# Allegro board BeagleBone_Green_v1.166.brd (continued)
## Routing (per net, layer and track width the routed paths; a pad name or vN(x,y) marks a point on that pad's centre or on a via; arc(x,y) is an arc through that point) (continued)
TIMER6: length 36.6
  TOP w0.121: v1(51.56,113.39) 51.05,112.88 51.05,110.08 50.8,109.83 50.8,102.84 50.32,102.36 50.32,100.74 U5.U6
  LYR4 w0.133: P8.10 32.38,116.69 49.53,116.69 50.29,115.93 50.29,114.66 v1(51.56,113.39)
TIMER7: length 34.1
  TOP w0.121: v1(49.52,99.94) U5.T7
  LYR3 w0.133: v1(49.52,99.94) 49.52,104.28 47.37,106.43 47.37,109.19 45.67,110.9 45.67,111.15 44.36,112.46 37.25,112.46 v1(36.32,113.39)
  LYR4 w0.133: v1(36.32,113.39) 35.81,113.89 30.99,113.89 29.97,114.91 29.97,116.56 P8.8
TXCLK: length 6.1
  TOP w0.121: U14.20 26.73,99.8 27.06,100.13 29.85,100.13 30,100.29 30.01,100.29 30.24,100.52 30.24,100.53 30.4,100.69 v1(30.61,100.69)
  BOTTOM w0.121: R134.2 v1(30.61,100.69)
TXN: length 20.3
  TOP w0.095: v1(22.67,97.19) 22.67,96.81 22.99,96.49 U14.28
  LYR3 w0.102: v1(22.67,97.19) 22.28,96.8 22.28,96.28 21.21,95.21 21.21,93.57 19.61,91.97 18.11,91.97 17.3,92.79 17.3,94.21 17.55,94.47 18.29,94.47 18.54,94.21 P5.6
  BOTTOM w0.095: R123.1 v1(22.67,97.19)
  BOTTOM w0.121: P5.6 C140.1
TXP: length 17.8
  TOP w0.095: U14.29 23.43,95.99 23.21,96.21 22.68,96.21 22.67,96.22 v1(22.67,96.24)
  LYR3 w0.102: v1(22.67,96.24) 21.51,95.08 21.51,93.45 19.74,91.67 17.98,91.67 16.99,92.66 16.99,95.89 P5.3
  BOTTOM w0.095: R122.1 v1(22.67,96.24)
  BOTTOM w0.121: C139.1 P5.3
U5_H18: length 4.2
  TOP w0.121: U5.H18 39.5,93.14 39.3,92.94 R28.1
U5_R13: length 8.5
  TOP w0.121: v1(43.92,99.14) U5.R13
  LYR3 w0.121: 44.11,101.79 44.32,101.58 44.32,99.54 v1(43.92,99.14)
  LYR3 w0.133: 44.11,101.79 43.66,102.24 43.66,104.35 v1(43.49,104.52)
  BOTTOM w0.133: R160.1 43.81,104.85 v1(43.49,104.52)
U5_T13: length 7.5
  TOP w0.121: v1(43.92,99.94) U5.T13
  LYR3 w0.133: v1(42.88,104.57) 42.89,104.56 42.89,104.43 43.4,103.92 43.4,101.89 43.92,101.37 v1(43.92,99.94)
  BOTTOM w0.133: v1(42.88,104.57) 42.93,104.62 R161.1
UART0_RX: length 28.4
  TOP w0.121: v1(42.32,90.34) U5.E15
  LYR4 w0.133: v1(45.01,76.45) 42.8,78.66 42.8,79.78 42.09,80.49 42.09,85.6 40.85,86.84 40.85,89.4 41.36,89.92 41.9,89.92 v1(42.32,90.34)
  BOTTOM w0.121: U15.6 54.62,76.8 53.72,77.7 51.56,77.7 50.71,76.85 45.4,76.85 v1(45.01,76.45)
UART0_TX: length 28.7
  TOP w0.121: v1(41.52,90.34) U5.E16
  LYR4 w0.133: v1(44.42,76.4) 42.56,78.26 42.56,79.38 41.81,80.14 41.81,85.5 40.59,86.72 40.59,89.51 41.41,90.34 v1(41.52,90.34)
  BOTTOM w0.121: v1(44.42,76.4) 44.42,76.78 44.81,77.17 50.52,77.17 51.31,77.95 53.98,77.95 54.62,77.3 U15.5
UART1_RXD: length 25.6
  TOP w0.121: v1(41.53,89.51) 41.53,89.55 U5.D16
  LYR4 w0.121: 42.11,86.77 41.92,86.96 41.92,89.12 v1(41.53,89.51)
  LYR4 w0.133: v1(46.48,74.02) 45.97,74.52 45.97,76.81 43.61,79.17 43.61,80.04 42.9,80.75 42.9,85.98 42.11,86.77
  BOTTOM w0.121: P9.26 50.16,70.97 49.15,70.97 47.75,72.36 47.75,73.25 46.99,74.02 v1(46.48,74.02)
UART1_TXD: length 23.3
  TOP w0.121: v1(42.32,89.54) U5.D15
  LYR4 w0.121: v1(42.32,89.54) 42.72,89.14 42.72,88.49
  LYR4 w0.133: P9.24 47.52,71.07 47.52,73.86 46.28,75.11 46.28,76.83 43.92,79.19 43.92,80.14 43.14,80.92 43.14,86.13 42.73,86.53 42.73,88.48 42.72,88.49
UART2_RXD: length 83.9
  TOP w0.121: v1(80.72,100.24) 79.44,101.53 J5.1 ; U5.A17 41.12,87.32 39.49,85.69 39.49,78.11 42.13,75.47 v1(42.13,75.34) 42.24,75.23 42.24,71.91 43.05,71.09 44.96,71.09 P9.22
  LYR3 w0.133: v1(42.13,75.34) 42.41,75.61 47.68,75.61 48.46,74.83 56,74.83 56.34,75.17 56.34,75.43 56.65,75.74 57.19,75.74 59.04,77.6 69.8,77.6 82.28,90.08 82.28,98.69 v1(80.72,100.24)
UART2_TXD: length 85.8
  TOP w0.121: v1(80.47,99.24) 80.18,99.53 J5.2 ; P9.21 45.21,68.3 45.21,69.95 44.45,70.71 42.93,70.71 41.91,71.73 41.91,74.9 v1(41.43,75.39) 39.24,77.57 39.24,85.83 40.72,87.3 40.72,87.94 U5.B17
  LYR3 w0.133: v1(80.47,99.24) 82.04,97.66 82.04,90.17 69.7,77.83 57.84,77.83 55.08,75.07 48.68,75.07 47.9,75.84 41.88,75.84 v1(41.43,75.39)
UART4_RXD: length 41.6
  TOP w0.121: v1(38.48,101.83) 38.61,101.7 38.61,101.47 38.91,101.17 38.91,101.12 40.1,99.94 40.72,99.94 U5.T17
  LYR4 w0.133: v1(38.48,101.83) 38.43,101.83 37.86,101.26 36.77,101.26 35.94,100.43 35.94,88.49 35.69,88.24 35.69,82.65 34.54,81.51 v1(34.54,71.6)
  BOTTOM w0.121: P9.11 35.05,68.3 35.05,70.52 34.54,71.03 v1(34.54,71.6)
UART4_TXD: length 44.2
  TOP w0.121: v1(33.66,71.6) 35.05,70.21 35.05,68.3 P9.13 ; v1(39.6,101.35) 39.6,101.34 39.75,101.19 39.75,101.07 40.08,100.74 40.71,100.74 U5.U17
  LYR4 w0.121: v1(39.6,101.35) 39.59,101.35
  LYR4 w0.133: v1(33.66,71.6) 33.66,81.64 35.18,83.16 35.18,88.49 35.43,88.75 35.43,101.06 37.58,103.2 38.28,103.2 38.89,102.59 38.89,101.78 39.32,101.35 39.59,101.35
USB0_DM: length 42.2
  TOP w0.114: U5.N18 40.2,97.25 40.05,97.25 39.79,97.51 39.47,97.51 39.32,97.36 38.99,97.36 38.84,97.51 38.58,97.51 38.43,97.36 38.18,97.36 37.46,98.07 37.46,99.12 36.97,99.62 36.75,99.62 36.58,99.8 36.58,100.01 36.35,100.23 36.09,100.23 35.92,100.41 35.92,100.67 35.04,101.55 33.08,101.55 32.65,101.98 22.83,101.98 16.89,107.92 14.53,107.92 14.41,107.81 14.41,107.25 14.2,107.04 U10.2 13.64,107.04 13.06,107.62 13.06,108.49 12.74,108.81 12.32,108.81 12.19,108.68 12.19,108.39 v1(12.19,108.39)
  BOTTOM w0.114: P4.2 11.97,108.61 v1(12.19,108.39)
USB0_DP: length 42.2
  TOP w0.114: v1(12.19,109.19) 12.29,109.09 12.85,109.09 13.34,108.61 13.34,107.74 13.54,107.54 U10.1 14.1,107.66 14.1,108 14.3,108.2 17.01,108.2 22.95,102.26 32.77,102.26 33.2,101.83 35.15,101.83 37.74,99.24 37.74,98.19 38.15,97.78 39.91,97.78 40.16,97.53 40.72,97.53 U5.N17
  BOTTOM w0.114: v1(12.19,109.19) 12.19,109.14 11.94,108.89 7.29,108.89 6.92,109.26 P4.3
USB0_ID: length 48.7
  TOP w0.121: v1(17.02,107.04) 16,106.02 14.1,106.02 13.98,106.15 U10.3 ; U5.P16 v1(41.52,98.34)
  LYR3 w0.133: v1(17.02,107.04) 17.1,106.95 27.15,106.95 27.76,106.35 31.7,106.35 32.56,105.49 36.25,105.49 36.91,104.83 38.02,104.83 38.89,103.96 38.89,101.27 39.54,100.62 41.31,100.62 41.54,100.39 41.65,100.39 41.89,100.15 41.89,98.71 v1(41.52,98.34)
  BOTTOM w0.121: v1(17.02,107.04) 16.94,107.11 16.94,108.1 14.76,110.29 7.26,110.29 6.89,109.91 P4.4
USB1_DM: length 54.2
  TOP w0.114: U5.R18 40.2,98.86 39.38,98.86 38.57,99.67 37.73,99.67 37.54,99.86 37.54,100.02 v1(37.62,100.1)
  LYR3 w0.127: v1(16.46,81.48) 16.46,81.41 16.18,81.13 15.82,81.13 15.39,81.55 15.39,83.31 18.39,86.31 19.66,86.31 22.66,89.31 22.66,92.23 23.47,93.04 23.47,101.04 25.12,102.69 34.7,102.69 36.02,101.37 36.91,101.37 37.36,100.91 37.36,100.51 37.62,100.25 v1(37.62,100.1)
  BOTTOM w0.114: P3.2 11.68,77.3 12.32,76.66 13.6,76.66 15.33,78.39 15.33,78.66 15.11,78.88 U9.2 15.11,79.58 15.27,79.73 15.91,79.73 16.08,79.9 16.08,81.21 16.36,81.48 v1(16.46,81.48)
USB1_DP: length 54.3
  TOP w0.114: U5.R17 41.04,98.74 40.64,99.14 39.5,99.14 38.53,100.1 v1(38.25,100.1)
  LYR3 w0.127: v1(38.25,100.1) 38.13,100.23 38.07,100.23 37.92,100.38 37.67,100.63 37.67,101.04 37.03,101.68 36.14,101.68 34.82,103 24.99,103 23.16,101.17 23.16,93.17 22.35,92.35 22.35,89.43 19.53,86.61 18.26,86.61 15.09,83.44 15.09,81.43 15.64,80.87 v1(16.54,80.87)
  BOTTOM w0.114: P3.3 12.12,76.38 13.72,76.38 15.61,78.27 U9.1 15.61,79.36 15.7,79.45 16.03,79.45 16.36,79.78 16.36,80.7 v1(16.54,80.87)
USB1_DRVVBUS: length 62.3
  TOP w0.121: U5.F15 v1(42.32,91.14)
  LYR3 w0.133: v1(3.68,71.73) 4.06,72.11 12.83,72.11 14.93,74.21 23.3,74.21 23.62,73.89 30.28,73.89 30.87,73.29 37.63,73.29 37.68,73.34 41.06,73.34 v1(41.25,73.53)
  LYR4 w0.121: v1(42.32,91.14) 41.69,91.14 40.33,89.77
  LYR4 w0.133: v1(41.25,73.53) 40.89,73.89 40.89,76.43 41.99,77.52 41.99,79.37 41.53,79.83 41.53,83.92 40.92,84.53 40.92,85.85 40.33,86.44 40.33,89.77
  BOTTOM w0.121: v1(3.68,71.73) 4.06,72.11 R53.1 4.36,72.15 U8.4
USB1_ID: length 1.9
  TOP w0.121: v1(40.72,98.34) 40.77,98.29 U5.P17
  BOTTOM w0.121: v1(40.72,98.34) 40.72,98.83 40.45,99.1 R49.2
USB1_OCN: length 65.1
  TOP w0.121: v1(41.48,99.98) 41.5,99.96 41.5,99.95 U5.T16
  LYR3 w0.121: 38.01,102.94 38.01,102.49 37.97,102.46 37.97,101.7 39.34,100.33 41.17,100.33
  LYR3 w0.133: 41.17,100.33 41.48,100.02 v1(41.48,99.98) ; v1(14.33,104.05) 18.28,104.05 18.36,104.14 23.11,104.14 23.2,104.05 35.78,104.05 36.6,103.23 37.72,103.23 38.01,102.94
  LYR4 w0.133: v1(14.33,104.05) 14.66,103.72 14.66,86.23 9.02,80.59 3.33,80.59 v1(3.17,80.75)
  BOTTOM w0.121: v1(3.17,80.75) 3.56,80.37 R52.2 3.94,79.77 4.36,79.35 U8.5
USB1_PWR: length 9.8
  LYR3 w0.381: v1(7.37,79.73) 8.76,79.73 10.67,81.64 v1(14.1,81.64)
  BOTTOM w0.254: U9.6 15.61,80.5 14.48,81.64 v1(14.1,81.64)
USB1_VBUS: length 55.1
  TOP w0.305: v1(37.59,102.59) 37.97,102.21 37.97,101.63 38.57,101.03 38.57,100.95 39.99,99.54 U5.T18
  LYR3 w0.381: v1(37.59,102.59) 37.52,102.67 36.55,102.67 35.56,103.66 24.69,103.66 22.94,101.9 v1(21.03,101.9)
  LYR4 w0.381: v1(21.72,90.14) 22.1,90.53 22.1,99.54 21.03,100.61 v1(21.03,101.9)
  BOTTOM w0.381: v1(21.72,90.14) 21.72,89.26 19.05,86.59 17.65,86.59 16.51,85.45 7.87,85.45 5.33,82.91 FB8.1
USB_DC: length 26.5
  TOP w0.254: v1(16.13,107.26) 16.05,107.26 15.78,107.54 U10.6
  LYR3 w0.381: v1(38.25,103.63) 38.25,103.78 37.64,104.39 36.7,104.39 36.12,104.98 32.49,104.98 31.72,105.74 30,105.74 29.68,105.41 28.01,105.41 27.03,106.4 16.89,106.4 16.13,107.16 v1(16.13,107.26)
  BOTTOM w0.381: R159.1 38.4,103.48 v1(38.25,103.63)
  vias: v1(20.7,76.53) v1(20.65,75.95) v1(21.21,76.17) v2(12.57,107.29) v2(12.6,106.27) v2(13.34,106.25)
USR0: length 25.9
  TOP w0.121: Q1.2 21.34,108.05 21.72,107.67 22.86,107.67 R76.1 24.03,107.16 26.04,105.16 26.04,104.78 27.61,103.2 35.38,103.2 36.3,104.11 38.35,104.11 38.73,103.73 38.73,103.61 39.42,102.92 41.27,102.92 42.72,101.48 U5.V15
USR1: length 30.5
  TOP w0.121: Q1.5 21.34,110.85 21.59,111.1 22.86,111.1 R77.1 24.13,109.83 24.13,107.47 26.31,105.28 26.31,104.88 27.74,103.45 35.2,103.45 36.12,104.37 38.48,104.37 39.52,103.33 41.25,103.33 43.12,101.46 43.12,100.74 U5.U15
USR2: length 31.6
  TOP w0.121: R78.1 19.94,106.53 v1(18.92,107.54) 18.67,107.8 Q2.2 ; U5.T15 42.31,99.94 v1(42.3,99.94)
  LYR3 w0.133: v1(42.3,99.94) 42.3,100.1 41.48,100.92 40.79,100.92 39.8,101.9 39.8,102.21 39.22,102.79 39.22,104.01 38.02,105.21 36.93,105.21 36.37,105.77 32.72,105.77 31.29,107.19 29.64,107.19 29.63,107.19 29.3,107.19 29.29,107.19 19.28,107.19 v1(18.92,107.54)
USR3: length 28.8
  TOP w0.121: U5.V16 41.92,101.93 41.2,102.64 39.2,102.64 38.61,103.23 38.09,103.23 38.06,103.26 37.35,103.26 37.32,103.29 35.85,103.29 35.51,102.95 27.44,102.95 25.55,104.84 25.55,105.26 24.21,106.6 22.66,106.6 22.58,106.53 R79.1 21.97,106.78 21.08,107.67 20.47,107.67 19.79,108.36 19.79,108.99 19.58,109.19 18.8,109.19 18.67,109.32 Q2.5
VDCDC1:
  vias: v1(21.46,75.03) v1(22.1,75.03)
VIO: length 22.4
  TOP w0.121: U2.18 24.06,76.8 23.56,76.3 v1(23.49,76.3) ; U16.5 33.8,73.25 33.11,73.94 32.08,73.94 v1(31.65,74.37)
  LYR3 w0.133: v1(23.49,76.3) 24.38,76.3 25.15,75.54 30.28,75.54 31.45,74.37 v1(31.65,74.37)
  BOTTOM w0.121: R7.2 17.78,80.59 19.53,78.84 21.84,78.84 22.61,78.08 23.11,78.08 23.49,77.7 v1(23.49,76.3)
VLDO1: length 4.5
  TOP w0.203: 20.45,81.77 U2.3
  TOP w0.254: v1(19.68,81.89) 19.81,81.77 20.45,81.77
  BOTTOM w0.381: v1(19.68,81.89) 19.05,81.25 18.8,81.25 18.8,83.03
VREFP_ADC: length 7.7
  TOP w0.121: 47.12,87.94 47.12,86.97 46.99,86.84
  TOP w0.254: 47.12,87.94 U5.B9
  TOP w0.305: 46.69,86.54 46.99,86.84
  TOP w0.381: C32.1 C31.1 C33.1 45.5,83.45 R27.2 45.5,84.66 46.61,85.77 46.61,86.46 46.69,86.54
VRTC: length 42.4
  TOP w0.254: v1(49.52,89.54) U5.D7
  LYR3 w0.381: v1(18.29,85.45) 21.97,85.45 22.35,85.83 26.92,85.83 28.7,87.6 34.54,87.6 36.57,85.58 38.83,85.58 38.84,85.57 38.99,85.57 39.77,84.79 47.48,84.79 48.7,86.02 v1(48.7,86.08)
  BOTTOM w0.178: R26.1 51.21,84.3 51.09,84.43 51.09,85.79 50.8,86.08 v1(50.61,86.08)
  BOTTOM w0.381: R5.2 C16.1 16.51,84.1 17.86,85.45 v1(18.29,85.45) ; C105.1 v1(48.7,86.08)
WAKEUP: length 63.4
  TOP w0.121: U5.C5 v1(51.12,88.73) ; v1(22.48,76.3) 22.48,76.3 22.06,76.72 U2.13
  LYR3 w0.133: v1(59.82,76.56) 57.38,74.12 48.03,74.12 47.37,74.78 43.1,74.78 42.75,74.42 35.84,74.42 35.23,73.81 31.24,73.81 30.53,74.52 25.53,74.52 24.26,75.79 22.98,75.79 v1(22.48,76.3)
  LYR4 w0.133: v1(51.12,88.73) 50.67,88.29 50.67,87.67 52.01,86.33 54.86,86.33 56.13,85.06 56.39,85.06 59.82,81.64 v1(59.82,76.56)
  BOTTOM w0.121: v1(51.12,88.73) 51.52,88.33 51.52,87.67 51.56,87.62 R26.2
WP: length 9.2
  BOTTOM w0.121: TP4.1 23.24,88.11 25.47,88.11 26.04,87.54 R156.2 26.82,87.54 26.95,87.67 26.95,88.39 27.2,88.64 28.83,88.64 29.48,87.99 U7.5
XDMA_EVENT_INTR0: length 10.7
  BOTTOM w0.121: P2.17 35.62,82.59 36.32,81.89 36.32,80.49 37.4,79.41 40.78,79.41 40.97,79.22 41.78,79.22 42.04,78.97 R18.2
YEL_C: length 3.2
  TOP w0.381: v1(5.71,93.07) 5.71,92.15 P5.11
  BOTTOM w0.381: R130.2 v1(5.71,93.07)
YELA: length 28.5
  TOP w0.254: U14.2 v1(25.23,92.56)
  BOTTOM w0.254: v1(25.23,92.56) 24.72,92.05 22.61,92.05 19.3,88.75 16.05,88.75 13.13,91.67 12.06,91.67 10.54,93.19 C164.1 C166.1 8.89,93.19 8.45,92.75 8.45,91.48 8,91.03 7.24,91.03 6.6,91.67 R135.1
  BOTTOM w0.381: P5.12 6.27,91.47 R135.1
ZQ: length 2.5
  TOP w0.121: v1(67.7,87.49) U12.L8
  BOTTOM w0.121: R99.2 68.1,87.09 v1(67.7,87.49)
N21757673: length 4.3
  BOTTOM w0.121: R11.2 C19.1 R10.1 17.53,104.62 18.29,105.38 U4.4
N21769115: length 5.9
  TOP w0.121: S2.3 S2.1 78.74,110.24 78.74,110.97 78.23,111.48 R75.2
N22155575: length 7
  TOP w0.121: v1(42.32,98.34) U5.P15
  LYR3 w0.133: v1(42.32,100.71) 42.32,100.66 42.71,100.27 42.71,98.73 v1(42.32,98.34)
  BOTTOM w0.381: R159.2 40.49,103.48 42.04,101.93 42.04,100.99 v1(42.32,100.71)
N22248684: length 1.5
  TOP w0.121: R167.1 39.88,107.92 40.58,107.23 Y4.3
N22287501: length 12.7
  TOP w0.121: v1(38.1,113.39) 38.48,113 42.04,113 42.37,112.67 U3.4
  BOTTOM w0.121: v1(38.1,113.39) 37.59,113.89 32.38,113.89 31.88,113.39 R162.1
N22287555: length 18.9
  TOP w0.121: v1(41.73,104.14) 41.38,103.78 39.45,103.78 37.46,105.77 37.46,107.47 39.07,109.07 41.53,109.07 41.72,109.26 U3.2 ; v1(43.12,99.14) U5.R14
  LYR3 w0.121: 43.52,100.81 43.52,99.54 v1(43.12,99.14)
  LYR3 w0.133: v1(41.73,104.14) 42.24,103.63 42.24,102.49 43.52,101.21 43.52,100.81
N22420400: length 9.6
  TOP w0.203: U2.4 20.3,81.37 20.19,81.25 20.48,80.97 U2.5
  TOP w0.381: 20.19,81.25 20.09,81.25 17.81,78.98 17.81,77.05 16.56,75.79 TP5.1
N22420444: length 10.1
  TOP w0.203: TP6.1 17.5,74.63 17.5,76.1 18.29,76.89 18.29,78.79 20.06,80.57 U2.6
N22420447: length 4.1
  TOP w0.203: TP7.1 18.67,75.95 19.99,77.27 19.99,77.88 20.68,78.57 U2.11
N22488252: length 24.6
  TOP w0.121: TP9.1 26.42,88.75 29.21,88.75 32.38,85.57 32.38,85.42 33.91,83.9 34.75,83.9 35.56,84.71 35.56,88.68 36.79,89.91 37.45,89.91 37.83,89.53 38.75,89.53 39.56,90.34 40.72,90.34 U5.E17
N22648410: length 8.6
  BOTTOM w0.121: U17.1 53.07,107.28 C25.1 53.72,107.29 R17.1 54.23,106.78 55.63,106.78 56.01,107.16 56.01,108.55 Y2.2
N22648422: length 8.2
  BOTTOM w0.121: U17.2 52.46,106.78 C26.1 53.85,106.15 R17.2 54.23,106.27 55.88,106.27 56.26,105.89 Y2.1
N22649826: length 1.5
  BOTTOM w0.121: U17.3 50.67,106.28 R171.2
N22650321: length 3.4
  BOTTOM w0.121: R174.1 R172.2 46.86,105.38 47.12,105.64 47.12,106.02 47.38,106.28 U17.6
N22650344: length 2.4
  BOTTOM w0.121: U17.7 46.73,106.78 R175.2 R173.1
N22650388: length 5.3
  TOP w0.121: U5.V10 46.61,101.24 46.61,102.72 46.99,103.1 v1(46.99,104.11)
  BOTTOM w0.121: v1(46.99,104.11) 46.99,104.75 47.37,105.13 47.37,105.64 47.51,105.78 U17.5

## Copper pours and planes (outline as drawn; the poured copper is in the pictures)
DGND on TOP (solid shape): 7.24,74.27 3.43,74.27 3.43,78.08 7.24,78.08
DGND on TOP: 29.16,86.97 30.35,86.97 32.13,85.19 32.13,84.81 33.66,83.29 33.66,80.9 33.4,80.65 29.87,80.65 29.69,80.82 29.69,81.76 29.79,81.86 30.78,81.86 31.06,82.14 31.06,83.24 28.98,85.32 28.98,86.79
DGND on TOP: 25.45,74.32 28.5,74.32 28.6,74.22 28.6,72.06 28.42,71.88 26.92,71.88 26.37,72.44 25.68,72.44 25.3,72.82 25.3,74.17
DGND on TOP: 15.11,85.83 19.81,85.83 19.94,85.7 19.94,84.3 19.3,83.67 18.16,83.67 17.65,83.16 17.65,81.38 17.4,81.13 15.24,81.13 14.86,80.75 13.59,80.75 13.46,80.87 13.46,84.18
DGND on TOP: 43.05,108.81 43.31,108.56 43.31,104.75 43.05,104.5 41.4,104.5 41.02,104.11 39.37,104.11 38.1,105.38 38.1,107.8 39.12,108.81
DGND on TOP: 59.79,100.51 68.76,100.51 71.98,97.28 71.98,80.87 71.15,80.04 63.78,80.04 59.66,75.92 57.02,75.92 56.69,76.25 56.69,76.84 56.9,77.04 57.38,77.04 57.61,77.27 57.61,78.69 57.73,78.82 58.27,78.82 60.25,80.8 60.25,81.1 60.53,81.38 68.17,81.38 69.39,82.6 69.39,96.22 66.14,99.47 60.99,99.47 60.88,99.36 60.07,99.36 59.59,99.85 59.59,100.3
DGND on TOP: 23.37,92.81 29.34,92.81 30.23,91.92 30.23,89.51 29.84,89.13 22.99,89.13 22.48,89.64 22.48,91.92
DGND on BOTTOM: 25.25,99.14 26.04,99.14 27.91,97.26 27.91,93.52 27.76,93.37 25.17,93.37 25.04,93.5 25.04,98.93
DGND on BOTTOM: 34.16,94.36 34.47,94.36 34.75,94.64 34.75,95.2 34.82,95.28 35.43,95.28 35.51,95.2 35.51,89.15 35.18,88.82 34.42,88.82 34.04,89.2 34.04,91.49 34.14,91.59 34.14,94.34
DGND on BOTTOM: 42.67,95.61 42.8,95.73 42.8,96.11 43.31,96.11 43.31,95.73 43.56,95.48 43.56,94.84 43.31,94.59 43.31,94.21 42.67,94.21
DGND on BOTTOM: 28.57,92.68 29.84,92.68 30.35,92.18 30.35,89.76 29.84,89.26 23.75,89.26 22.86,90.14 22.86,91.41 23.24,91.8 27.69,91.8 27.83,91.94 27.83,92.37 28.09,92.63 28.52,92.63
DGND on BOTTOM: 53.64,102.08 68.12,102.08 71.45,98.76 71.45,96.37 73,94.82 73,78.77 72.42,78.18 63.63,78.18 61.59,80.21 58.27,80.21 57,81.48 53.92,81.48 53.16,82.25 53.16,84.58 53.77,84.58 54.1,84.25 55.55,84.25 58.62,81.18 69.14,81.18 69.65,81.69 69.65,82.85 69.55,82.96 69.55,83.34 70.03,83.82 70.03,90.91 70,90.93 70.51,91.44 70.69,91.44 70.69,92.91 70.05,93.55 70.05,96.19 70.13,96.27 70.13,96.65 69.27,97.51 67.26,97.51 65.35,99.42 54.41,99.42 53.29,100.53 53.29,101.73
DGND on BOTTOM: 20.95,81.19 20.95,80.87 21.29,80.54 22.05,80.54 22.35,80.24 22.35,78.51 22.48,78.38 22.48,78.33 23.94,78.33 24.51,78.91 25.53,78.91 25.78,79.16 25.78,79.79 26.54,79.79 26.54,79.54 26.8,79.29 27.43,79.29 27.69,79.54 27.69,81.71 27.48,81.92 26.7,81.92 26.54,81.76 26.54,80.94 25.78,80.94 25.78,81.69 25.58,81.89 24.87,81.89 24.64,81.66 24.64,80.94 23.88,80.94 23.88,81.66 23.67,81.86 22.86,81.86 22.73,81.74 22.73,80.94 21.97,80.94 21.97,81.58 21.77,81.79 21.03,81.79 20.95,81.71 20.95,81.56 20.96,81.55 20.96,81.2
DGND on LYR2_GND: 11.56,68.62 14.1,71.16 17.91,71.16 19.49,69.57 19.49,67.03 20.13,66.4 75.37,66.4 76.66,66.63 77.91,67.03 78.55,67.67 78.55,73.38 80.1,74.93 84.35,74.93 85.53,76.11 85.53,85.13 86.03,85.62 86.03,95.75 85.53,96.24 85.53,109.26 84.9,109.89 78.87,109.89 78.55,110.21 78.55,117.2 77.91,117.83 76.53,118.35 75.06,118.47 20.13,118.47 19.49,117.83 19.49,115.29 17.91,113.7 14.1,113.7 12.51,115.29 12.51,117.51 12.19,117.83 7.75,117.83 4.6,116.53 3.3,113.39 3.3,105.13 3.94,104.5 13.46,104.5 14.1,103.86 14.1,101.96 13.46,101.32 11.87,101.32 10.6,102.59 3.94,102.59 3.3,101.96 3.3,96.56 3.94,95.92 3.94,94.02 3.3,93.38 3.3,87.99 3.94,87.35 10.6,87.35 11.87,88.62 13.46,88.62 14.1,87.99 14.1,86.08 13.46,85.45 3.94,85.45 3.05,84.56 3.05,74.27 3.3,74.02 3.3,70.52 5.21,68.62
DGND on LYR3: 59.72,100.99 68.07,100.99 71.93,97.13 71.93,84.51 68,80.57 56.97,80.57 56.39,81.15 56.39,81.99 56.52,82.12 57,82.12 57.61,81.51 57.61,81.41 57.96,81.05 66.17,81.05 67.95,82.83 67.95,95.35 63.55,99.75 59.59,99.75 59.31,100.03 59.31,100.58
DGND on LYR3: 39.62,105.64 41.66,105.64 42.29,105 42.29,104.62 42.04,104.37 41.53,104.37 41.4,104.24 41.4,103.23 41.91,102.72 41.91,101.57 41.66,101.32 40.39,101.32 40,101.7 40,103.35 39.37,103.99 39.37,105.38
DGND on LYR5_PWR: 32.26,73 39.62,73 40.77,71.86 40.77,69.95 41.02,69.7 61.98,69.7 62.61,70.33 62.61,80.72 62.79,80.9 71.7,80.9 72.42,81.61 72.42,99.29 70.74,100.97 70.74,105.21 70.76,105.23 72.57,105.23 74.42,103.38 78.18,103.38 79.2,104.39 84.81,104.39 85.29,103.91 85.29,93.65 86,92.94 86,85.95 85.62,85.57 85.62,76.56 84.1,75.03 79.83,75.03 78.44,73.63 78.44,67.87 76.96,66.4 25.27,66.4 24.89,66.78 24.89,70.33 25.91,71.35 30.61,71.35
GND_EARTH on TOP: 7.75,65.76 3.71,67.43 2.03,71.48 2.03,113.39 3.71,117.43 7.75,119.1 75.06,119.1 83.59,115.57 87.12,107.04 87.12,77.83 83.59,69.29 75.06,65.76 ; 1 cut-out
GND_EARTH on BOTTOM: 7.75,65.76 3.71,67.43 2.03,71.48 2.03,113.39 2.09,114.19 2.26,114.99 2.26,115.11 2.32,115.17 4.4,118.01 7.75,119.1 75.06,119.1 82.5,116.53 86.77,109.93 86.82,109.88 86.82,109.73 87.05,108.39 87.12,107.04 87.12,77.83 83.59,69.29 75.06,65.76 ; 1 cut-out
GND_EARTH on LYR2_GND, LYR3, LYR4: 7.75,65.76 3.71,67.43 2.03,71.48 2.03,113.39 3.71,117.43 7.75,119.1 75.06,119.1 83.59,115.57 87.12,107.04 87.12,77.83 83.59,69.29 75.06,65.76 ; 1 cut-out
GND_EARTH on LYR5_PWR: 7.75,65.76 3.71,67.43 2.03,71.48 2.03,113.39 3.71,117.43 7.75,119.1 75.06,119.1 83.59,115.57 87.12,107.04 87.12,77.83 83.59,69.29 75.06,65.76 ; 1 cut-out
GND_OSC0 on BOTTOM: 45.47,109.7 53.72,109.7 54.36,110.34 57.91,110.34 58.29,109.96 58.29,103.61 57.91,103.23 54.48,103.23 53.21,104.5 52.83,104.5 51.69,103.35 44.2,103.35 44.07,103.48 44.07,108.31 ; 1 cut-out
GND_OSC1 on TOP: 49.66,75.29 49.91,75.03 55.12,75.03 55.37,75.29 55.37,82.91 54.48,83.79 53.72,83.79 52.45,85.06 52.45,86.97 51.56,87.86 50.29,87.86 50.16,87.73 50.16,85.32 49.53,84.68 49.53,83.79 49.66,83.67
VBUS on BOTTOM: 8.38,81.69 10.19,81.69 10.64,82.14 12.12,82.14 12.73,81.53 12.73,79.63 12.42,79.32 8.38,79.32 8,79.71 8,81.31
VDD_1V8 on LYR3: 41.68,97.38 34.42,97.38 34.16,97.64 34.16,99.42 34.42,99.67 41.4,99.67 41.81,99.26 41.81,97.51
VDD_1V8 on LYR4: 47.12,90.27 46.86,90.02 43.05,90.02 42.8,90.27 42.8,93.57 42.55,93.83 41.4,93.83 41.15,94.08 41.15,99.42 41.4,99.67 43.94,99.67 44.2,99.92 44.2,100.38 44.58,100.76 46.53,100.76 47.12,100.18 47.12,94.84 46.74,94.46 46.74,94.21 47.12,93.83
VDD_1V8 on LYR5_PWR: 46.1,79.1 46.1,90.4 46.23,90.53 48.13,90.53 48.26,90.4 48.26,85.57 48.64,85.19 50.29,85.19 50.55,84.94 50.55,79.1 50.29,78.84 46.35,78.84
VDD_1V8 on LYR5_PWR: 33.91,99.42 33.66,99.16 33.66,93.32 30.99,90.65 30.99,90.4 29.08,88.49 29.08,86.97 27.81,85.7 27.81,82.65 28.07,82.4 32.13,82.4 32.38,82.65 32.38,85.7 35.18,88.49 35.18,99.16 34.92,99.42
VDD_3V3A on BOTTOM: 49.53,98.15 51.43,98.15 51.69,98.4 51.69,100.3 52.15,100.77 52.15,101.57 51.69,101.57 51.69,100.94 51.31,100.56 51.31,99.03 50.93,99.03 50.93,100.56 50.55,100.94 50.55,101.57 50.09,101.57 50.09,100.99 49.66,100.56 49.66,98.78 49.4,98.53 49.4,98.27
VDD_3V3A on BOTTOM: 41.27,94.84 41.78,94.84 42.16,94.46 42.16,94.21 42.42,93.95 43.05,93.95 43.31,93.7 43.31,92.68 42.8,92.68 42.8,93.07 42.42,93.45 41.91,93.45 41.66,93.7 40,93.7 40,94.21 40.64,94.21
VDD_3V3A on BOTTOM: 43.69,101.57 43.69,100.94 43.31,100.56 43.31,98.4 43.56,98.15 44.7,98.15 44.83,98.27 44.83,98.4 44.45,98.78 44.45,100.69 44.16,100.98 44.16,101.57
VDD_3V3A on LYR5_PWR: 22.99,76.81 22.73,77.06 22.73,88.49 22.99,88.75 28.57,88.75 28.83,88.49 28.83,87.22 27.56,85.95 27.56,82.52 27.94,82.14 32.26,82.14 32.64,82.52 32.64,85.57 35.43,88.37 35.43,99.16 34.67,99.92 33.91,99.92 33.66,100.18 33.66,102.21 39.24,107.8 39.24,111.1 39.5,111.35 42.67,111.35 42.93,111.1 42.93,110.08 43.18,109.83 50.93,109.83 53.59,112.5 70.05,112.5 70.61,111.94 70.61,108.69 69.95,108.03 69.95,101.3 69.01,100.36 55.65,100.36 55.24,99.95 55.24,99.92 54.99,99.67 51.94,99.67 51.56,99.29 51.56,96.62 50.55,95.61 50.55,94.59 50.29,94.34 43.94,94.34 43.43,93.83 43.43,93.45 43.31,93.32 42.04,93.32 41.78,93.07 41.78,92.43 42.04,92.18 43.31,92.18 43.56,91.92 43.56,91.67 42.55,90.65 42.55,90.02 42.8,89.76 44.2,89.76 44.45,90.02 44.45,90.4 44.58,90.53 45.72,90.53 45.85,90.4 45.85,78.97 46.23,78.59 50.29,78.59 50.55,78.33 50.55,70.71 50.29,70.46 41.27,70.46 41.02,70.71 41.02,76.43 40.64,76.81
VDD_3V3B on TOP: 83.06,107.14 83.54,106.65 84.96,106.65 85.22,106.91 85.42,106.91 85.62,106.71 85.62,105.99 84.91,105.28 78.38,105.28 77.29,104.19 76.15,104.19 75.82,104.52 75.82,106.1 76.15,106.43 79.27,106.43 79.98,107.14
VDD_3V3B on BOTTOM: 26.48,100.37 25.53,100.37 25.53,101.04 25.3,101.27 25.3,103.12 25.58,103.4 26.97,103.4 27.75,102.63 27.75,98.66 27.14,98.66 26.48,99.32
VDD_3V3B on LYR5_PWR: 20.13,66.4 19.49,67.03 19.49,69.57 17.91,71.16 14.1,71.16 11.56,68.62 5.21,68.62 3.3,70.52 3.3,84.81 3.94,85.45 13.46,85.45 14.1,86.08 14.1,88.11 14.35,88.37 19.18,88.37 22.86,92.05 24.64,92.05 25.02,92.43 25.02,102.08 24.64,102.46 14.35,102.46 14.1,102.72 14.1,103.86 13.46,104.5 3.94,104.5 3.3,105.13 3.3,113.39 4.6,116.53 7.75,117.83 12.19,117.83 12.51,117.51 12.51,115.29 14.1,113.7 17.91,113.7 19.49,115.29 19.49,117.83 20.13,118.47 76.01,118.47 77.91,117.83 78.55,117.2 78.55,110.21 78.87,109.89 83.95,109.89 84.73,109.11 84.73,104.93 84.43,104.62 78.74,104.62 77.83,103.71 74.98,103.71 73.08,105.61 71.09,105.61 70.43,106.27 70.43,107.31 70.97,107.85 70.97,112.17 70.38,112.75 53.47,112.75 50.8,110.08 43.43,110.08 43.18,110.34 43.18,111.35 42.93,111.61 39.24,111.61 38.99,111.35 38.99,107.92 33.4,102.34 33.4,93.57 28.83,89 22.86,89 22.48,88.62 22.48,76.94 22.86,76.56 40.45,76.56 40.77,76.24 40.77,70.84 40.45,70.52 27.43,70.52 27.11,70.21 27.11,66.71 26.8,66.4
VDD_5V on TOP: 20.66,78.86 20.66,79.07 19.2,79.07 18.64,78.51 18.64,77.42 18.8,77.27 19.65,77.27 19.75,77.37 19.75,78.11 20.51,78.86
VDD_5V on BOTTOM: 18.06,78.77 19.13,78.77 19.33,78.56 20.17,78.56 20.4,78.33 20.4,77.27 19.81,76.68 18.16,76.68 17.91,76.94 17.91,77.42 17.93,77.44 17.93,78.64
VDD_5V on LYR4: 19.71,78.46 20.09,78.08 20.09,73.94 20.69,73.34 22.9,73.34 24.43,71.81 25.96,71.81 27.71,70.05 27.71,66.83 27.08,66.19 25.6,66.19 24.59,67.21 24.59,67.23 24.16,67.23 23.14,68.25 20.04,68.25 16.97,71.32 16.97,77.88 17.55,78.46
VDD_CORE on TOP: 28.7,79.22 28.7,78.08 28.96,77.83 32.03,77.83 32.89,78.69 32.89,79.86 32.77,79.98 28,79.98 27.88,79.87 27.3,79.87 27.3,79.67 28.26,79.67
VDD_CORE on BOTTOM: 35.92,95.25 36.37,95.25 37.29,94.34 37.29,89.89 37.13,89.74 36.83,89.74 36.68,89.59 36.68,89 36.55,88.87 35.94,88.87 35.79,89.03 35.79,95.12
VDD_CORE on LYR3: 50.55,90.65 47.37,90.65 47.12,90.91 47.12,92.05 46.74,92.43 43.81,92.43 43.56,92.18 43.56,89.26 43.31,89 34.16,89 33.4,89.76 33.4,90.78 33.91,91.29 34.67,91.29 34.92,91.54 34.92,92.56 35.18,92.81 41.66,92.81 41.66,94.34 42.55,94.34 42.55,95.35 41.91,95.35 41.4,95.86 41.4,96.24 41.78,96.62 42.8,96.62 43.18,97 44.83,97 46.61,98.78 50.55,98.78 50.8,98.53 50.8,90.91
VDD_MPU on TOP: 36.73,87.73 37.69,87.73 37.92,87.5 37.92,86.56 37.59,86.23 36.68,86.23 36.45,86.46 36.45,87.45
VDD_MPU on TOP: 26.61,76.87 26.42,76.87 26.42,77.51 27.11,77.51 27.94,76.68 30.23,76.68 30.86,76.05 30.86,73.25 30.48,72.87 29.34,72.87 29.08,73.13 29.08,74.27 28.57,74.78 27.74,74.78 27.3,75.21 27.3,76.17
VDD_MPU on BOTTOM: 27.48,75.44 28.6,75.44 28.85,75.18 28.85,72.97 28.65,72.77 27.58,72.77 27.36,73 27.36,75.31
VDD_MPU on LYR3: 46.86,86.21 46.86,91.92 46.61,92.18 43.94,92.18 43.81,92.05 43.81,88.75 42.67,87.6 37.34,87.6 37.21,87.48 37.21,86.46 37.34,86.33 41.53,86.33 41.91,85.95 46.61,85.95
VDD_PHYA on BOTTOM: 22.96,103.12 24.69,103.12 24.84,102.97 24.84,100.97 24.54,100.66 24.54,99.26 24.79,99.01 24.79,93.09 24.46,92.76 23.75,92.76 23.34,93.17 23.34,97.1 22.5,97.94 22.5,102.67
VDD_PHYA on LYR5_PWR: 11.94,88.62 10.67,87.35 3.94,87.35 3.3,87.99 3.3,93.38 3.94,94.02 3.94,95.92 3.3,96.56 3.3,101.96 3.94,102.59 10.67,102.59 11.94,101.32 13.46,101.32 14.35,102.21 24.51,102.21 24.76,101.96 24.76,92.56 24.51,92.3 22.73,92.3 19.05,88.62
VDD_PLL on BOTTOM: 49.91,85.19 49.91,87.86 50.16,88.11 50.16,90.27 49.91,90.53 49.15,90.53 48.89,90.27 48.89,86.33 49.4,85.83 49.4,85.19
VDD_PLL on BOTTOM: 44.96,98.65 45.47,98.15 45.59,98.15 46.48,99.03 46.48,99.29 46.1,99.67 46.1,100.56 45.37,101.29 45.37,101.57 44.86,101.57 44.86,100.91 44.96,100.81
VDD_PLL on BOTTOM: 39.88,93.19 40.51,93.19 40.64,93.32 42.16,93.32 42.42,93.07 42.42,92.43 42.16,92.18 41.02,92.18 40.51,92.68 39.88,92.68
VDD_PLL on LYR4: 41.15,93.32 42.29,93.32 42.55,93.07 42.55,92.43 42.29,92.18 40,92.18 39.75,92.43 39.75,96.75 39.88,96.88 40.77,96.88 40.89,96.75 40.89,93.57
VDD_PLL on LYR5_PWR: 42.04,92.56 42.16,92.43 43.81,92.43 44.07,92.68 47.75,92.68 48.51,91.92 48.51,90.27 48.64,90.14 50.29,90.14 50.55,90.4 50.55,93.83 50.29,94.08 44.07,94.08 43.69,93.7 43.69,93.32 43.43,93.07 42.16,93.07 42.04,92.94
VDDS on BOTTOM: 49.28,100.62 49.66,101 49.66,101.7 49.53,101.83 48.01,101.83 47.75,101.57 47.75,100.69 47.88,100.69 48.13,100.43 48.13,99.03 47.75,98.65 47.75,98.27 47.88,98.15 48.64,98.15 49.28,98.78
VDDS on BOTTOM: 40,87.73 40.77,87.73 41.02,87.99 41.02,88.75 41.27,89 42.67,89 42.93,89.26 42.93,89.64 43.05,89.76 43.31,89.76 43.43,89.89 43.43,90.53 43.31,90.65 42.67,90.65 41.91,91.41 41.02,91.41 40.77,91.16 40.77,90.4 40.51,90.14 39.88,90.14 39.88,87.86
VDDS on LYR4: 47.62,90.78 47.37,91.03 47.37,93.95 47.12,94.21 47.12,94.46 47.37,94.72 47.37,99.67 47.62,99.92 50.55,99.92 50.8,99.67 50.8,89.38 50.55,89.13 49.4,89.13 49.15,89.38 49.15,90.53 48.89,90.78
VDDS on LYR5_PWR: 44.07,90.02 42.93,90.02 42.8,90.14 42.8,90.53 43.81,91.54 43.81,92.05 44.2,92.43 47.62,92.43 48.26,91.8 48.26,90.91 48.13,90.78 44.45,90.78 44.2,90.53 44.2,90.14
VDDS_DDR on BOTTOM: 19.86,73.61 20.52,73.61 20.68,73.46 20.68,72.69 20.88,72.49 21.46,72.49 22.12,71.83 23.32,71.83 23.55,72.06 23.55,72.39 23.7,72.54 24.94,72.54 25.12,72.36 25.12,71.25 24.69,70.82 20.55,70.82 19.71,71.65 19.71,73.46
VDDS_DDR on LYR3: 61.72,67.98 61.4,67.67 20.07,67.67 19.81,67.92 19.81,73.51 20.07,73.76 28.57,73.76 29.87,72.47 61.14,72.47 61.72,71.88
VDDS_DDR on LYR5_PWR: 50.8,95.48 50.8,90.4 51.05,90.14 51.43,90.14 51.69,89.89 51.69,85.83 50.8,84.94 50.8,70.97 51.24,70.52 61.72,70.52 62.04,70.84 62.04,81 62.36,81.32 71.56,81.32 71.88,81.64 71.88,99.1 71.56,99.42 71.5,99.42 70.87,100.05 55.75,100.05 55.12,99.42 52.07,99.42 51.82,99.16 51.82,96.49
P_L1 on TOP: 24.58,76.18 24.58,75.86 24,75.29 23.62,75.29 23.49,75.16 23.49,74.9 23.75,74.65 24.89,74.65 25.15,74.9 25.15,76.24 24.89,76.49
P_L1 on BOTTOM: 23.29,75.44 24.51,75.44 24.79,75.16 24.79,72.92 24.64,72.77 23.42,72.77 23.16,73.03 23.16,75.31
P_L2 on TOP: 26.04,74.65 25.78,74.9 25.78,75.79 25.91,75.92 25.91,76.59 26.04,76.72 26.12,76.72 26.92,75.92 26.92,74.9 26.67,74.65
P_L2 on BOTTOM: 25.45,75.49 26.72,75.49 26.87,75.34 26.87,73.13 26.52,72.77 25.37,72.77 25.15,73 25.15,75.18
P_L3 on TOP: 27.84,80.47 27.3,80.47 27.3,80.68 28.13,80.68 28.7,81.25 28.7,82.65 28.96,82.91 30.73,82.91 30.86,82.78 30.86,82.27 30.73,82.14 29.59,82.14 29.46,82.02 29.46,80.87 28.96,80.37 27.94,80.37
RXP on BOTTOM (solid shape): 16.02,99.42 15.24,98.7 14.56,99.38 14.54,99.42 14.56,99.46 15.24,100.14
SYS_5V on TOP: 15.49,80.49 16.99,80.49 17.4,80.9 18.54,80.9 18.75,80.7 18.75,80.52 18.05,79.82 18.05,79.79 17.45,79.2 17.45,77.65 17.25,77.44 15.39,77.44 15.11,77.17 15.11,73 14.41,72.3 14.16,72.3 13.72,71.86 10.92,71.86 10.41,72.36 7.24,72.36 6.99,72.62 6.99,73.63 7.75,74.4 9.53,74.4 10.54,75.41 12.19,75.41 12.7,75.92 12.7,78.84 13.84,79.98 14.99,79.98
SYS_5V on BOTTOM: 4.95,74.65 5.71,74.65 5.84,74.52 5.84,72.87 5.97,72.75 6.86,72.75 7.24,73.13 7.24,74.02 7.49,74.27 8.51,74.27 8.64,74.14 8.64,72.36 7.24,70.97 5.59,70.97 4.83,71.73 4.83,74.52
SYS_5V on LYR3: 26.42,84.68 27.81,83.29 27.81,82.91 28.83,81.89 28.83,80.37 26.16,77.7 26.16,76.05 26.04,75.92 25.27,75.92 24.51,76.68 23.11,76.68 20.07,79.73 19.81,79.73 18.87,78.79 18.47,78.79 17.6,77.93 14.5,77.93 14.27,78.16 14.27,78.77 14.96,79.45 16.87,79.45 18.41,81 18.41,82.27 19.18,83.03 22.86,83.03 23.88,84.05 23.88,84.18 24.38,84.68
USB1_PWR on BOTTOM: 4.72,80.77 6.1,80.77 6.43,80.44 6.86,80.44 6.93,80.37 7.49,80.37 7.75,80.11 7.75,79.32 8.13,78.94 9.47,78.94 9.96,78.46 9.96,77.7 9.45,77.19 7.24,77.19 6.81,77.62 4.95,77.62 4.88,77.7 4.88,79.6 4.6,79.88 4.6,80.65
USB_DC on TOP: 20.83,78.28 21.51,78.28 21.59,78.21 21.59,77.95 21.72,77.83 21.72,76.05 21.34,75.67 21.29,75.67 21.03,75.41 21.03,74.63 21.44,74.22 21.44,73.1 21.26,72.92 19.99,72.92 19.79,73.13 19.79,76.56 20.37,77.14 20.37,77.83
USB_DC on BOTTOM: 20.45,75.67 20.19,75.92 20.19,76.68 20.83,77.32 20.83,78.33 20.95,78.46 21.97,78.46 22.35,78.08 22.35,76.68 22.22,76.56 22.22,76.05 21.84,75.67
USB_DC on BOTTOM: 5.36,108.18 8.23,108.18 8.81,107.59 12.6,107.59 13.18,108.18 16.05,108.18 16.36,107.87 16.36,107.11 16.26,107.01 15.54,107.01 15.37,106.83 15.37,106.53 15.11,106.27 14.61,106.27 14.1,105.77 7.87,105.77 6.99,106.65 6.99,106.73 6.17,107.54 6.17,107.59 6.12,107.59 5.97,107.75 5.38,107.75 5.28,107.85 5.28,108.1
USB_DC on LYR4: 20.47,75.51 21.59,75.51 21.97,75.9 21.97,76.17 22.35,76.56 22.35,83.16 21.72,83.79 21.72,99.42 20.45,100.69 20.45,103.73 16.13,108.05 11.81,108.05 11.3,107.54 11.3,105.38 11.81,104.88 14.22,104.88 14.86,104.24 14.86,102.84 18.41,99.29 18.41,80.37 20.32,78.46 20.32,77.83 20.35,77.83 20.35,75.64
VDCDC1 on TOP: 21.91,75.86 23.62,75.86 24.36,76.59 24.36,77.31 24.56,77.31 24.56,76.41 24.38,76.24 24.38,75.92 23.88,75.41 23.24,75.41 22.99,75.16 22.99,74.9 22.73,74.65 21.46,74.65 21.21,74.9 21.21,75.29 21.72,75.79 21.84,75.79
VDCDC1 on BOTTOM: 22.61,75.13 22.61,73.05 22.38,72.82 21.34,72.82 21.16,73 21.16,73.53 20.75,73.94 19.99,73.94 19.81,74.12 19.81,74.88 20.35,75.41 22.33,75.41
VRTC on LYR3: 49.91,89.76 49.15,89.76 48.89,89.51 48.89,86.72 48.51,86.33 48.51,85.95 48.64,85.83 50.67,85.83 50.8,85.95 50.8,86.33 50.16,86.97 50.16,89.51
VRTC on LYR5_PWR: 48.77,85.45 50.93,85.45 51.43,85.95 51.43,89.76 51.31,89.89 48.64,89.89 48.51,89.76 48.51,85.7

Small or netless copper shapes (teardrops, artwork), in the pictures only: 288 on TOP, 185 on BOTTOM, 86 on LYR3, 46 on LYR4

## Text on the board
BOTTOM: LAYER 6 | SOLDER
Board Geometry/Soldermask Bottom: SMS
Ref Des/Silkscreen Bottom: microSD Card | USB | S/N | BSLK
Board Geometry/Outline: V_CUT
TOP: BeagleBone_Green | B | v1 | LAYER 1 | COMPONENT
Board Geometry/Soldermask Top: SMC
Ref Des/Silkscreen Top: PWR | USER | RESET | POWER | AM335x | TXD | 3V3 | SDA | GND | RXD | SCL | USB Host | 10/100 Ethernet | (OZ) | LAYER 1 - PRIMARY SIDE - SIGNAL | LAYER 2 - GROUND PLANE | LAYER 3 - SIGNAL | LAYER 4 - SIGNAL | LAYER 5 - SPLIT POWER PLANE | LAYER 6 - SECONDARY SIDE - SIGNAL | LAYER# | COPPER WEIGHT | HALF+PLATING | IMPEDANCE CONTROL | +/- 10% | 50ohm SINGLE ENDED | TRACE WIDTH | TRACE WIDTH / SPACE | 90ohm DIFFERENTIAL | 100ohm DIFFERENTIAL | TSLK | 1 | 5.25 | 4.75 | 4.5/6.5 | 5.0/7.0 | 3.75/7.25 | 4.00/8.00 | LAYER STACK-UP - ALL DIMENSIONS IN INCHES
LYR2_GND: LAYER 2 | GROUND
LYR3: LAYER 3 | SIGNAL
LYR4: LAYER 4 | SIGNAL
LYR5_PWR: LAYER 5 | POWER
DISPLAY_TOP: SPC
DISPLAY_BOTTOM: SPS
DIMENSION: R.250 2X
USER_PART_NUM_TOP: TSLKC
USER_PART_NUM_BOTTOM: BSLKC
User.13: C100 | C73 | C97 | C98 | C99 | C25 | C48 | C46 | C58 | C41 | C66 | C65 | C60 | C70 | C26 | C87 | C45 | C79 | C54 | C44 | C82 | C83 | R49 | C84 | C69 | R158 | C71 | C86 | C85 | C67 | C38 | C78 | C52 | C53 | C51 | R116 | R131 | R140 | R134 | R145 | R113 | R138 | R115 | R112 | R114 | R117 | C134 | R150 | R154 | R155 | R153 | C154 | R151 | R152 | C68 | C43 | C50 | C81 | C56 | C42 | C47 | R17 | C49 | C72 | C88 | C106 | C94 | C63 | C80 | FB1 | C40 | C39 | D2 | D3 | D4 | D5 | USER LEDS | 0 | 1 | 2 | 3 | D1 | RESET | C19 | R10 | R72 | R73 | R74 | R71 | POWER | R9 | R7 | U10 | C1 | TP5 | TP6 | C16 | C3 | R5 | TP7 | TP8 | TP9 | C9 | C12 | P | R119 | R118 | A | R139 | R133 | R128 | R127 | R126 | R125 | R124 | R28 | 14 | 18 | U3 | Y4 | R27 | TP3 | V | TP1 | C96 | 16 | TP2 | 64 | 17 | 32 | 49 | 33 | R157 | R95 | C61 | R166 | D8 | 46 | 45 | U9 | 19 | R147 | R146 | C117 | C119 | R96 | R99 | C120 | C121 | C116 | C118 | FB7 | C151 | C114 | C115 | C122 | FB8 | R98 | C123 | R100 | C124 | R97 | C109 | C110 | C112 | C113 | C107 | C108 | C111 | R22 | C28 | U15 | FB2 | U6 | FB3 | C64 | C77 | R14 | C24 | C30 | L3 | U7 | C135 | C136 | R103 | C14 | C8 | L2 | R108 | R156 | R159 | C126 | C133 | C132 | C131 | C13 | FB4 | C7 | L1 | R144 | R129 | R123 | R122 | R121 | R120 | U4 | C137 | C140 | C138 | C139 | C141 | R137 | R11 | C17 | 5 | R135 | C2 | R12 | R132 | R130 | C | E | G | J | L | N | R | 7 | 9 | PWR | TP4 | R8 | Q2 | Q1 | C18 | R3 | R4 | C11 | C37 | C55 | U16 | C29 | R50 | R24 | R23 | R25 | C32 | C165 | C31 | C57 | R29 | C33 | C27 | R81 | R80 | R84 | C93 | R45 | R48 | R82 | R46 | R47 | R165 | R83 | C168 | C166 | R85 | C167 | C157 | R86 | R87 | R88 | R89 | R90 | R91 | C169 | C156 | C160 | C163 | R92 | R93 | R94 | R75 | C173 | C153 | R52 | C35 | C171 | R53 | C76 | C149 | R148 | R149 | C150 | C148 | C147 | C146 | R70 | R69 | R68 | R67 | C145 | C144 | R66 | R65 | R64 | R63 | C172 | C155 | FB5 | C75 | R62 | C95 | C103 | R61 | R101 | R60 | C170 | C102 | R105 | R58 | C162 | R30 | R102 | C101 | R57 | C161 | C22 | R110 | R54 | R59 | R106 | C74 | C21 | R26 | R109 | R55 | C164 | C104 | R164 | R21 | R56 | C92 | R163 | C105 | C89 | C91 | C90 | C59 | R20 | R19 | R167 | R18 | C158 | R51 | C159 | 20 | R160 | C62 | R161 | C125 | C130 | C129 | R162 | R111 | R104 | C128 | C152 | C127 | R107 | C143 | C15 | R142 | R1 | R141 | R143 | R6 | C4 | C10 | C142 | R77 | C36 | R76 | R79 | R78 | C20 | R136 | DATE | DESIGN ENGR | PROJECT ENGR | ENGR MGR | NEXT ASSEMBLY | APPROVED | CHECKED | DRAFTING | ENGR | 1 OF 1 | USB | S1 | P1 | P5 | U13 | U2 | U14 | Y3 | U5 | J1 | Y1 | AM335x | C34 | U11 | U12 | RT1 | D7 | D6 | S2 | P3 | P8 | P9 | USB Host | HDMI | P6 | P10 | U8 | S/N | Y2 | P4 | S3 | 10/100 Ethernet | microSD Card | P2 | ASSEMBLY SOLDER SIDE
User.14: NONE
User.27: FIGURE | SIZE | 8.0 | 12.0 | 30.0 | 36.0 | 40.0 | 63.0 | 92.0 | 125.0 | 24.0 | 80.0 | 128.0 | 42.0x20.0 | DRILL CHART: TOP to BOTTOM | ALL UNITS ARE IN MILS | TOLERANCE | +3.0/-3.0 | +0.0/-0.0 | +5.0/-5.0 | PLATED | NON-PLATED | QTY | 814 | 28 | 97 | 4 | 20 | 2
